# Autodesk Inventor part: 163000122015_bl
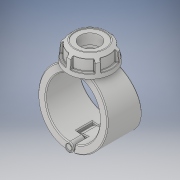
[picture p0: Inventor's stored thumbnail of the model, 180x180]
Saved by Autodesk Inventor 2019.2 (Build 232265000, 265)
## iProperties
Created: 2022-02
Part Number: 163000122015_bl
Material: Generic
Description: Plassadle Threaded 122x1 1/2''
Document SubType Name: Modeling
Designer: comp2
Density: 1 g/cm^3
Appearance: Default
Author: comp2
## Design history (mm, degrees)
derived "16300.ipt"
feature "Solid1::16300.ipt" dims "ScaleForDerivedMember" = 10
feature "Solid2::16300.ipt" dims "ScaleForDerivedMember" = 10
feature "Solid3::16300.ipt" dims "ScaleForDerivedMember" = 10
feature "Solid4::16300.ipt" dims "ScaleForDerivedMember" = 10
tag "TaggingFeature1"
body "Solid1"
body "Solid2"
body "Solid3"
body "Solid4"
other parameters: "d0" = 122 [user parameter], "d2" = 157 [user parameter], "d3" = 61 [user parameter], "d7" = 149.15 [user parameter], "d8" = 85 deg [user parameter], "d9" = 45 deg [user parameter], "d10" = 102 [user parameter], "d11" = 49 [user parameter], "d12" = 29.2495 [user parameter], "d13" = 42.84 [user parameter], "d14" = 67.2675 [user parameter], "d42" = 3.5 [user parameter], "d49" = 3.14 [user parameter], "d51" = 0 [user parameter], "d52" = 24.5 [user parameter], "d53" = 86.35 [user parameter], "d54" = 35 [user parameter], "d55" = 0 [user parameter], "d59" = 0 [user parameter], "d61" = 0 [user parameter], "d62" = 35 [user parameter], "d63" = 0 [user parameter], "d65" = 0 [user parameter], "d67" = 0 [user parameter], "d69" = 0 [user parameter], "d70" = 1 [user parameter], "d71" = 96 [user parameter], "d72" = 0 [user parameter], "d73" = 2 [user parameter], "d78" = 86.7 [user parameter], "d79" = 5.1 [user parameter], "d80" = 60 deg [user parameter], "d81" = 5.1 [user parameter], "d84" = 0 [user parameter], "d85" = 1 [user parameter], "d87" = 360 deg [user parameter], "d122" = 52 [user parameter], "d124" = 42.80128 [user parameter], "d125" = 2.08925 [user parameter], "d127" = 198 [user parameter], "d129" = 44.845 [user parameter], "d130" = 38.11825 [user parameter], "d131" = 33.8 [user parameter], "d132" = 45 deg [user parameter], "d133" = 23.66 [user parameter], "d134" = 22.4225 [user parameter], "d136" = 0 [user parameter], "d138" = 0 [user parameter], "d" = 122 [user parameter], "d1" = 25 [user parameter], "B" = 157 [user parameter], "E_" = 54 [user parameter], "E1" = 102 [user parameter], "H1" = 198 [user parameter], "H2" = 52 [user parameter], "H3" = 78 [user parameter], "H_costum" = 49 [user parameter], "Rp" = 44.845 [user parameter], "d128" = 41.785 [user parameter]
